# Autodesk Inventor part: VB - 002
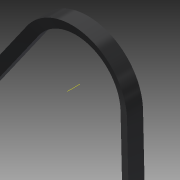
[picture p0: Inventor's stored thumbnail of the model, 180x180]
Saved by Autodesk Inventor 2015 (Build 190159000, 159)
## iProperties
Created: 2007-02
Part Number: VB - 002
Material: Rubber
Document SubType Name: Modeling
Designer: Autodesk, Inc.
Density: 0.93 g/cm^3
Description: =VBelt - <Material>
Mass: 125.388 g
Surface Area: 636.681 cm^2
Volume: 134.825 cm^3
Appearance: Rubber - Black - Version 1.1
CustomPartVersion: 1
Author: Autodesk, Inc.
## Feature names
1. Belt
## Parameters: d0 = 0, da_Alfa = 40 deg, da_H = 7.9375 mm, da_Bw = 10.6172 mm, da_Hw = 2.6822 mm, d1 = 10.6172 mm, d2 = 7.9375 mm, d3 = 2.6822 mm, d5 = 40 deg, d6 = 0, d7 = 0, d8 = 0, d10 = 0, d11 = 0, d12 = 0
